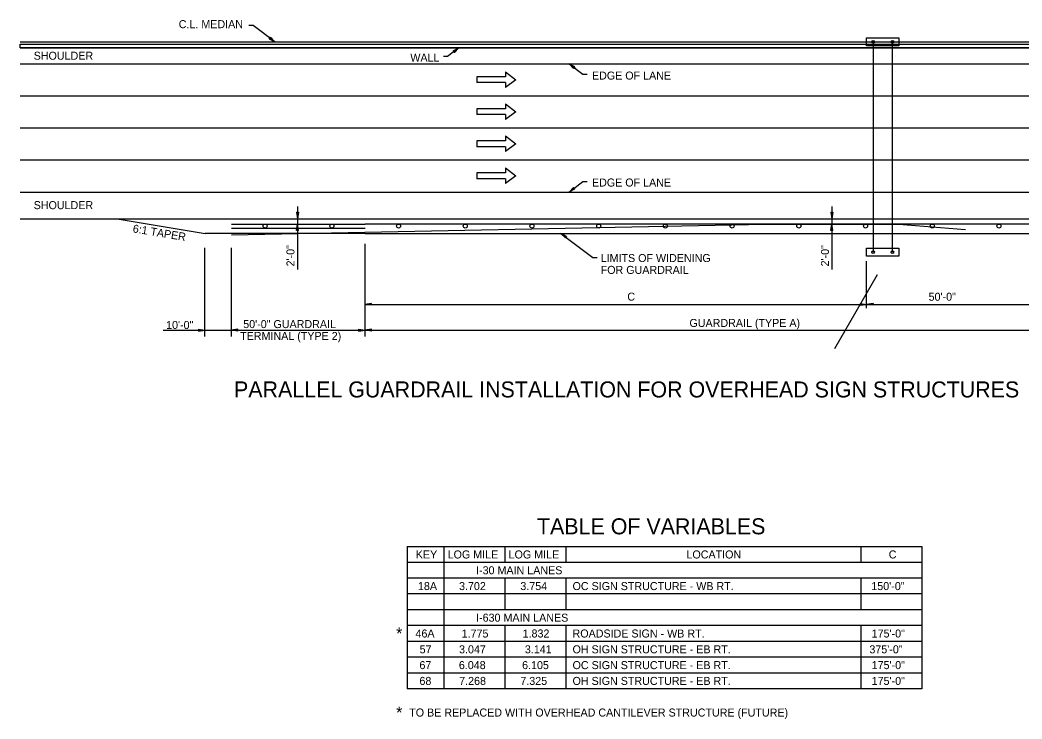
# Model space of a CAD drawing. Extents: x 1373853 to 1374003, y 380191 to 380927.
# Drawn here: x 1373877.3 to 1373952.4, y 380689.2 to 380741.6 of the extents above; entities that cross this region are included whole.
import ezdxf

# ---------------------------------------------------------------- set-up
doc = ezdxf.new("R2010")
doc.units = 0
for name, color, linetype in [('2', 7, 'Continuous'), ('44', 7, 'Continuous'), ('7', 7, 'Continuous'), ('8', 7, 'Continuous'), ('Default', 7, 'Continuous'), ('E_Existing ROW', 7, 'Continuous'), ('Plan Notes', 7, 'Continuous'), ('R_Draft', 7, 'Continuous'), ('R_Proposed Road', 7, 'Continuous'), ('R_SIGN_OH', 7, 'Continuous')]:
    doc.layers.add(name, color=color, linetype=linetype)

msp = doc.modelspace()

# ---------------------------------------------------------------- linework, layer by layer
at = {"layer": '2'}
for p, q in [((1373894.796, 380741.159), (1373894.477, 380741.159)), ((1373896.424, 380739.928), (1373894.796, 380741.159)), ((1373910.216, 380739.478), (1373909.369, 380738.838)), ((1373909.369, 380738.838), (1373909.05, 380738.838)), ((1373918.466, 380738.278), (1373919.498, 380737.498)), ((1373919.498, 380737.498), (1373919.818, 380737.498)), ((1373918.466, 380728.678), (1373919.498, 380729.459)), ((1373919.498, 380729.459), (1373919.818, 380729.459)), ((1373898.109, 380727.602), (1373898.109, 380722.881)), ((1373938.173, 380727.602), (1373938.173, 380722.881)), ((1373917.854, 380725.578), (1373920.253, 380723.765)), ((1373903.176, 380717.856), (1373903.176, 380724.807)), ((1373891.176, 380717.856), (1373891.176, 380724.492)), ((1373893.176, 380717.856), (1373893.176, 380724.492)), ((1373920.253, 380723.765), (1373920.572, 380723.765)), ((1373940.776, 380719.97), (1373940.776, 380723.499)), ((1373903.176, 380720.26), (1373967.577, 380720.26)), ((1373888.057, 380718.335), (1373962.85, 380718.335))]:
    msp.add_line(p, q, dxfattribs=at)
at = {"layer": '44'}
msp.add_line((1373877.32, 380726.678), (1373970.938, 380726.678), dxfattribs=at)
at = {"layer": '7'}
for p, q in [((1373895.997, 380740.16), (1373896.083, 380740.272)), ((1373895.997, 380740.16), (1373896.424, 380739.928)), ((1373896.003, 380740.167), (1373896.359, 380739.975)), ((1373896.012, 380740.177), (1373896.291, 380740.026)), ((1373896.019, 380740.187), (1373896.229, 380740.073)), ((1373896.028, 380740.197), (1373896.166, 380740.122)), ((1373896.032, 380740.21), (1373896.099, 380740.17)), ((1373896.048, 380740.225), (1373896.099, 380740.17)), ((1373896.054, 380740.235), (1373896.166, 380740.122)), ((1373896.061, 380740.242), (1373896.229, 380740.073)), ((1373896.065, 380740.252), (1373896.291, 380740.026)), ((1373896.074, 380740.265), (1373896.359, 380739.975)), ((1373896.083, 380740.272), (1373896.424, 380739.928)), ((1373909.789, 380739.247), (1373910.216, 380739.478)), ((1373909.789, 380739.247), (1373909.876, 380739.134)), ((1373909.795, 380739.239), (1373910.151, 380739.432)), ((1373909.804, 380739.229), (1373910.083, 380739.381)), ((1373909.811, 380739.219), (1373910.021, 380739.334)), ((1373909.82, 380739.209), (1373909.958, 380739.285)), ((1373909.824, 380739.197), (1373909.891, 380739.236)), ((1373909.84, 380739.182), (1373909.891, 380739.236)), ((1373909.847, 380739.172), (1373909.958, 380739.285)), ((1373909.853, 380739.164), (1373910.021, 380739.334)), ((1373909.858, 380739.154), (1373910.083, 380739.381)), ((1373909.866, 380739.142), (1373910.151, 380739.432)), ((1373909.876, 380739.134), (1373910.216, 380739.478)), ((1373918.893, 380738.047), (1373918.466, 380738.278)), ((1373918.806, 380737.934), (1373918.466, 380738.278)), ((1373918.886, 380738.039), (1373918.531, 380738.232)), ((1373918.815, 380737.942), (1373918.531, 380738.232)), ((1373918.824, 380737.954), (1373918.598, 380738.181)), ((1373918.877, 380738.029), (1373918.598, 380738.181)), ((1373918.871, 380738.019), (1373918.661, 380738.134)), ((1373918.828, 380737.964), (1373918.661, 380738.134)), ((1373918.835, 380737.972), (1373918.723, 380738.085)), ((1373918.862, 380738.009), (1373918.723, 380738.085)), ((1373918.842, 380737.982), (1373918.791, 380738.036)), ((1373918.858, 380737.997), (1373918.791, 380738.036)), ((1373918.893, 380738.047), (1373918.806, 380737.934)), ((1373918.806, 380729.022), (1373918.466, 380728.678)), ((1373918.893, 380728.91), (1373918.466, 380728.678)), ((1373918.815, 380729.015), (1373918.531, 380728.725)), ((1373918.886, 380728.917), (1373918.531, 380728.725)), ((1373918.824, 380729.002), (1373918.598, 380728.776)), ((1373918.877, 380728.927), (1373918.598, 380728.776)), ((1373918.828, 380728.992), (1373918.661, 380728.823)), ((1373918.871, 380728.937), (1373918.661, 380728.823)), ((1373918.835, 380728.985), (1373918.723, 380728.872)), ((1373918.862, 380728.947), (1373918.723, 380728.872)), ((1373918.842, 380728.975), (1373918.791, 380728.92)), ((1373918.858, 380728.96), (1373918.791, 380728.92)), ((1373918.893, 380728.91), (1373918.806, 380729.022)), ((1373898.035, 380727.158), (1373898.109, 380726.678)), ((1373898.035, 380727.158), (1373898.181, 380727.158)), ((1373898.05, 380727.158), (1373898.109, 380726.759)), ((1373898.062, 380727.158), (1373898.109, 380726.841)), ((1373898.074, 380727.158), (1373898.109, 380726.922)), ((1373898.086, 380727.158), (1373898.109, 380727.001)), ((1373898.097, 380727.158), (1373898.109, 380727.082)), ((1373898.181, 380727.158), (1373898.109, 380726.678)), ((1373898.131, 380727.158), (1373898.109, 380727.001)), ((1373898.155, 380727.158), (1373898.109, 380726.841)), ((1373898.169, 380727.158), (1373898.109, 380726.759)), ((1373898.145, 380727.158), (1373898.109, 380726.922)), ((1373898.119, 380727.158), (1373898.109, 380727.082)), ((1373938.099, 380727.158), (1373938.173, 380726.678)), ((1373938.099, 380727.158), (1373938.245, 380727.158)), ((1373938.114, 380727.158), (1373938.173, 380726.759)), ((1373938.126, 380727.158), (1373938.173, 380726.841)), ((1373938.138, 380727.158), (1373938.173, 380726.922)), ((1373938.15, 380727.158), (1373938.173, 380727.001)), ((1373938.161, 380727.158), (1373938.173, 380727.082)), ((1373938.245, 380727.158), (1373938.173, 380726.678)), ((1373938.195, 380727.158), (1373938.173, 380727.001)), ((1373938.219, 380727.158), (1373938.173, 380726.841)), ((1373938.233, 380727.158), (1373938.173, 380726.759)), ((1373938.209, 380727.158), (1373938.173, 380726.922)), ((1373938.183, 380727.158), (1373938.173, 380727.082)), ((1373898.038, 380725.798), (1373898.109, 380726.278)), ((1373898.181, 380725.798), (1373898.109, 380726.278)), ((1373938.102, 380725.798), (1373938.173, 380726.278)), ((1373938.245, 380725.798), (1373938.173, 380726.278)), ((1373898.181, 380725.798), (1373898.038, 380725.798)), ((1373898.05, 380725.798), (1373898.109, 380726.197)), ((1373898.062, 380725.798), (1373898.109, 380726.116)), ((1373898.074, 380725.798), (1373898.109, 380726.035)), ((1373898.086, 380725.798), (1373898.109, 380725.953)), ((1373898.097, 380725.798), (1373898.109, 380725.875)), ((1373898.169, 380725.798), (1373898.109, 380726.197)), ((1373898.157, 380725.798), (1373898.109, 380726.116)), ((1373898.145, 380725.798), (1373898.109, 380726.035)), ((1373898.133, 380725.798), (1373898.109, 380725.953)), ((1373898.121, 380725.798), (1373898.109, 380725.875)), ((1373918.281, 380725.347), (1373917.854, 380725.578)), ((1373918.194, 380725.234), (1373917.854, 380725.578)), ((1373918.274, 380725.339), (1373917.919, 380725.532)), ((1373918.203, 380725.242), (1373917.919, 380725.532)), ((1373938.245, 380725.798), (1373938.102, 380725.798)), ((1373938.114, 380725.798), (1373938.173, 380726.197)), ((1373938.126, 380725.798), (1373938.173, 380726.116)), ((1373938.138, 380725.798), (1373938.173, 380726.035)), ((1373938.15, 380725.798), (1373938.173, 380725.953)), ((1373938.161, 380725.798), (1373938.173, 380725.875)), ((1373938.233, 380725.798), (1373938.173, 380726.197)), ((1373938.221, 380725.798), (1373938.173, 380726.116)), ((1373938.209, 380725.798), (1373938.173, 380726.035)), ((1373938.197, 380725.798), (1373938.173, 380725.953)), ((1373938.185, 380725.798), (1373938.173, 380725.875)), ((1373918.212, 380725.254), (1373917.986, 380725.481)), ((1373918.265, 380725.329), (1373917.986, 380725.481)), ((1373918.259, 380725.319), (1373918.049, 380725.434)), ((1373918.216, 380725.264), (1373918.049, 380725.434)), ((1373918.223, 380725.272), (1373918.111, 380725.385)), ((1373918.25, 380725.309), (1373918.111, 380725.385)), ((1373918.23, 380725.282), (1373918.179, 380725.336)), ((1373918.246, 380725.297), (1373918.179, 380725.336)), ((1373918.281, 380725.347), (1373918.194, 380725.234)), ((1373903.653, 380720.331), (1373903.176, 380720.26)), ((1373903.653, 380720.188), (1373903.176, 380720.26)), ((1373903.653, 380720.319), (1373903.254, 380720.26)), ((1373903.653, 380720.2), (1373903.254, 380720.26)), ((1373903.653, 380720.307), (1373903.338, 380720.26)), ((1373903.653, 380720.212), (1373903.338, 380720.26)), ((1373903.653, 380720.295), (1373903.419, 380720.26)), ((1373903.653, 380720.224), (1373903.419, 380720.26)), ((1373903.653, 380720.283), (1373903.498, 380720.26)), ((1373903.653, 380720.236), (1373903.498, 380720.26)), ((1373903.653, 380720.269), (1373903.579, 380720.26)), ((1373903.653, 380720.248), (1373903.579, 380720.26)), ((1373903.653, 380720.188), (1373903.653, 380720.331)), ((1373940.296, 380720.334), (1373940.776, 380720.26)), ((1373940.296, 380720.334), (1373940.296, 380720.188)), ((1373940.296, 380720.319), (1373940.694, 380720.26)), ((1373940.296, 380720.307), (1373940.613, 380720.26)), ((1373940.296, 380720.295), (1373940.532, 380720.26)), ((1373940.296, 380720.283), (1373940.453, 380720.26)), ((1373940.296, 380720.272), (1373940.372, 380720.26)), ((1373940.296, 380720.188), (1373940.776, 380720.26)), ((1373940.296, 380720.238), (1373940.453, 380720.26)), ((1373940.296, 380720.214), (1373940.613, 380720.26)), ((1373940.296, 380720.2), (1373940.694, 380720.26)), ((1373940.296, 380720.224), (1373940.532, 380720.26)), ((1373940.296, 380720.25), (1373940.372, 380720.26)), ((1373941.256, 380720.334), (1373940.776, 380720.26)), ((1373941.256, 380720.188), (1373940.776, 380720.26)), ((1373941.256, 380720.319), (1373940.857, 380720.26)), ((1373941.256, 380720.2), (1373940.857, 380720.26)), ((1373941.256, 380720.307), (1373940.938, 380720.26)), ((1373941.256, 380720.214), (1373940.938, 380720.26)), ((1373941.256, 380720.295), (1373941.019, 380720.26)), ((1373941.256, 380720.224), (1373941.019, 380720.26)), ((1373941.256, 380720.283), (1373941.098, 380720.26)), ((1373941.256, 380720.238), (1373941.098, 380720.26)), ((1373941.256, 380720.272), (1373941.179, 380720.26)), ((1373941.256, 380720.25), (1373941.179, 380720.26)), ((1373941.256, 380720.334), (1373941.256, 380720.188)), ((1373890.696, 380718.407), (1373891.176, 380718.335)), ((1373890.696, 380718.407), (1373890.696, 380718.263)), ((1373890.696, 380718.395), (1373891.094, 380718.335)), ((1373890.696, 380718.383), (1373891.011, 380718.335)), ((1373890.696, 380718.371), (1373890.932, 380718.335)), ((1373890.696, 380718.359), (1373890.853, 380718.335)), ((1373890.696, 380718.347), (1373890.772, 380718.335)), ((1373890.696, 380718.263), (1373891.176, 380718.335)), ((1373890.696, 380718.311), (1373890.853, 380718.335)), ((1373890.696, 380718.287), (1373891.011, 380718.335)), ((1373890.696, 380718.275), (1373891.094, 380718.335)), ((1373890.696, 380718.299), (1373890.932, 380718.335)), ((1373890.696, 380718.323), (1373890.772, 380718.335)), ((1373893.653, 380718.407), (1373893.176, 380718.335)), ((1373893.653, 380718.263), (1373893.176, 380718.335)), ((1373893.653, 380718.395), (1373893.254, 380718.335)), ((1373893.653, 380718.275), (1373893.254, 380718.335)), ((1373893.653, 380718.383), (1373893.338, 380718.335)), ((1373893.653, 380718.287), (1373893.338, 380718.335)), ((1373893.653, 380718.371), (1373893.419, 380718.335)), ((1373893.653, 380718.299), (1373893.419, 380718.335)), ((1373893.653, 380718.359), (1373893.498, 380718.335)), ((1373893.653, 380718.311), (1373893.498, 380718.335)), ((1373893.653, 380718.345), (1373893.579, 380718.335)), ((1373893.653, 380718.323), (1373893.579, 380718.335)), ((1373893.653, 380718.263), (1373893.653, 380718.407)), ((1373902.696, 380718.407), (1373903.176, 380718.335)), ((1373902.696, 380718.407), (1373902.696, 380718.263)), ((1373902.696, 380718.395), (1373903.094, 380718.335)), ((1373902.696, 380718.383), (1373903.011, 380718.335)), ((1373902.696, 380718.371), (1373902.932, 380718.335)), ((1373902.696, 380718.359), (1373902.853, 380718.335)), ((1373902.696, 380718.347), (1373902.772, 380718.335)), ((1373902.696, 380718.263), (1373903.176, 380718.335)), ((1373902.696, 380718.311), (1373902.853, 380718.335)), ((1373902.696, 380718.287), (1373903.011, 380718.335)), ((1373902.696, 380718.275), (1373903.094, 380718.335)), ((1373902.696, 380718.299), (1373902.932, 380718.335)), ((1373902.696, 380718.323), (1373902.772, 380718.335)), ((1373903.653, 380718.407), (1373903.176, 380718.335)), ((1373903.653, 380718.263), (1373903.176, 380718.335)), ((1373903.653, 380718.395), (1373903.254, 380718.335)), ((1373903.653, 380718.275), (1373903.254, 380718.335)), ((1373903.653, 380718.383), (1373903.338, 380718.335)), ((1373903.653, 380718.287), (1373903.338, 380718.335)), ((1373903.653, 380718.371), (1373903.419, 380718.335)), ((1373903.653, 380718.299), (1373903.419, 380718.335)), ((1373903.653, 380718.359), (1373903.498, 380718.335)), ((1373903.653, 380718.311), (1373903.498, 380718.335)), ((1373903.653, 380718.345), (1373903.579, 380718.335)), ((1373903.653, 380718.323), (1373903.579, 380718.335)), ((1373903.653, 380718.263), (1373903.653, 380718.407))]:
    msp.add_line(p, q, dxfattribs=at)
at = {"layer": 'Default'}
for p, q in [((1373913.712, 380737.683), (1373913.712, 380737.316)), ((1373913.712, 380737.683), (1373914.475, 380737.096)), ((1373913.712, 380737.316), (1373911.551, 380737.316)), ((1373911.551, 380737.316), (1373911.551, 380736.875)), ((1373913.712, 380736.875), (1373911.551, 380736.875)), ((1373914.475, 380737.096), (1373913.712, 380736.508)), ((1373913.712, 380736.875), (1373913.712, 380736.508)), ((1373913.712, 380735.283), (1373913.712, 380734.916)), ((1373913.712, 380735.283), (1373914.475, 380734.696)), ((1373913.712, 380734.916), (1373911.551, 380734.916)), ((1373911.551, 380734.916), (1373911.551, 380734.475)), ((1373914.475, 380734.696), (1373913.712, 380734.108)), ((1373913.712, 380734.475), (1373911.551, 380734.475)), ((1373913.712, 380734.475), (1373913.712, 380734.108)), ((1373913.712, 380732.516), (1373911.551, 380732.516)), ((1373911.551, 380732.516), (1373911.551, 380732.075)), ((1373913.712, 380732.883), (1373913.712, 380732.516)), ((1373913.712, 380732.883), (1373914.475, 380732.296)), ((1373914.475, 380732.296), (1373913.712, 380731.708)), ((1373913.712, 380732.075), (1373911.551, 380732.075)), ((1373913.712, 380732.075), (1373913.712, 380731.708)), ((1373913.712, 380730.116), (1373911.551, 380730.116)), ((1373911.551, 380730.116), (1373911.551, 380729.675)), ((1373913.712, 380730.483), (1373913.712, 380730.116)), ((1373913.712, 380730.483), (1373914.475, 380729.896)), ((1373913.712, 380729.675), (1373911.551, 380729.675)), ((1373914.475, 380729.896), (1373913.712, 380729.308)), ((1373913.712, 380729.675), (1373913.712, 380729.308))]:
    msp.add_line(p, q, dxfattribs=at)
at = {"layer": 'E_Existing ROW'}
msp.add_lwpolyline([(1373938.379, 380716.957), (1373941.576, 380722.493)], dxfattribs=at)
msp.add_lwpolyline([(1373938.379, 380716.957), (1373941.576, 380722.493)], dxfattribs=at)
at = {"layer": 'Plan Notes'}
for p, q in [((1373906.332, 380702.112), (1373944.903, 380702.112)), ((1373906.332, 380702.112), (1373906.332, 380691.451)), ((1373909.089, 380702.112), (1373909.089, 380691.451)), ((1373913.658, 380702.112), (1373913.658, 380700.928)), ((1373918.228, 380702.112), (1373918.228, 380700.928)), ((1373940.333, 380702.112), (1373940.333, 380700.928)), ((1373944.903, 380702.112), (1373944.903, 380691.451)), ((1373913.658, 380699.743), (1373913.658, 380697.374)), ((1373918.228, 380699.743), (1373918.228, 380697.374)), ((1373940.333, 380699.743), (1373940.333, 380697.374)), ((1373913.658, 380696.19), (1373913.658, 380691.451)), ((1373918.228, 380696.19), (1373918.228, 380691.451)), ((1373940.333, 380696.19), (1373940.333, 380691.451))]:
    msp.add_line(p, q, dxfattribs=at)
for points in [[(1373944.903, 380700.928), (1373906.332, 380700.928)], [(1373944.903, 380699.743), (1373906.332, 380699.743)], [(1373944.903, 380698.559), (1373906.332, 380698.559)], [(1373944.903, 380697.374), (1373906.332, 380697.374)], [(1373944.903, 380696.19), (1373906.332, 380696.19)], [(1373944.903, 380695.005), (1373906.332, 380695.005)], [(1373944.903, 380693.82), (1373906.332, 380693.82)], [(1373944.903, 380692.636), (1373906.332, 380692.636)], [(1373944.903, 380691.451), (1373906.332, 380691.451)]]:
    msp.add_lwpolyline(points, dxfattribs=at)
at = {"layer": 'R_Draft'}
msp.add_lwpolyline([(1373877.32, 380739.748), (1373970.938, 380739.748), (1373970.938, 380739.478), (1373877.32, 380739.478)], close=True, dxfattribs=at)
at = {"layer": 'R_Proposed Road'}
for p, q in [((1373877.32, 380739.928), (1373970.938, 380739.928)), ((1373877.32, 380739.748), (1373970.938, 380739.748)), ((1373877.32, 380739.478), (1373970.938, 380739.478)), ((1373877.32, 380738.278), (1373970.938, 380738.278)), ((1373877.32, 380735.878), (1373970.938, 380735.878)), ((1373877.32, 380733.478), (1373970.938, 380733.478)), ((1373877.32, 380731.078), (1373970.938, 380731.078)), ((1373877.32, 380728.678), (1373970.938, 380728.678)), ((1373884.594, 380726.676), (1373891.194, 380725.576)), ((1373893.174, 380726.276), (1373903.176, 380726.278)), ((1373893.176, 380725.478), (1373933.176, 380726.278)), ((1373933.176, 380726.278), (1373943.176, 380726.278)), ((1373943.176, 380726.278), (1373948.176, 380725.878)), ((1373903.196, 380725.578), (1373891.194, 380725.576)), ((1373893.174, 380725.979), (1373903.176, 380725.981))]:
    msp.add_line(p, q, dxfattribs=at)
for points in [[(1373905.692, 380726.278), (1373903.176, 380726.278)], [(1373908.192, 380726.278), (1373905.692, 380726.278)], [(1373910.692, 380726.278), (1373908.192, 380726.278)], [(1373915.692, 380726.278), (1373910.692, 380726.278)], [(1373918.192, 380726.278), (1373915.692, 380726.278)], [(1373920.692, 380726.278), (1373918.192, 380726.278)], [(1373925.692, 380726.278), (1373920.692, 380726.278)], [(1373928.192, 380726.278), (1373925.692, 380726.278)], [(1373930.692, 380726.278), (1373928.192, 380726.278)], [(1373933.176, 380726.278), (1373930.692, 380726.278)], [(1373935.692, 380726.278), (1373933.176, 380726.278)], [(1373938.192, 380726.278), (1373935.692, 380726.278)], [(1373940.692, 380726.278), (1373938.192, 380726.278)], [(1373958.176, 380725.878), (1373953.176, 380726.278), (1373940.692, 380726.278)], [(1373903.196, 380725.578), (1373933.183, 380725.578)], [(1373933.183, 380725.578), (1373960.176, 380725.578)]]:
    msp.add_lwpolyline(points, dxfattribs=at)
for centre in [(1373895.692, 380726.129), (1373900.692, 380726.129), (1373905.692, 380726.129), (1373910.692, 380726.129), (1373915.692, 380726.129), (1373920.692, 380726.129), (1373925.692, 380726.129), (1373930.692, 380726.129), (1373935.692, 380726.129), (1373940.692, 380726.129), (1373945.692, 380726.129), (1373950.692, 380726.129)]:
    msp.add_circle(centre, 0.15, dxfattribs=at)
at = {"layer": 'R_SIGN_OH'}
for p, q in [((1373940.776, 380740.228), (1373943.176, 380740.228)), ((1373940.776, 380739.628), (1373940.776, 380740.228)), ((1373941.251, 380739.928), (1373941.251, 380735.878)), ((1373942.701, 380735.878), (1373942.701, 380739.928)), ((1373943.176, 380740.228), (1373943.176, 380739.628)), ((1373943.176, 380739.628), (1373940.776, 380739.628)), ((1373941.251, 380735.878), (1373941.251, 380724.178)), ((1373942.701, 380724.178), (1373942.701, 380735.878)), ((1373940.776, 380724.478), (1373943.176, 380724.478)), ((1373940.776, 380723.878), (1373940.776, 380724.478)), ((1373943.176, 380724.478), (1373943.176, 380723.878)), ((1373943.176, 380723.878), (1373940.776, 380723.878))]:
    msp.add_line(p, q, dxfattribs=at)
for centre in [(1373941.251, 380739.928), (1373942.701, 380739.928), (1373941.251, 380724.178), (1373942.701, 380724.178)]:
    msp.add_circle(centre, 0.1, dxfattribs=at)

# ---------------------------------------------------------------- texts
at = {"layer": '2'}
for s, height, rotation, p in [('C.L. MEDIAN', 0.6, 0.00003, (1373889.217, 380740.955)), ('SHOULDER', 0.6, 0.00003, (1373878.343, 380738.591)), ('WALL', 0.6, 359.99997, (1373906.573, 380738.442)), ('EDGE OF LANE', 0.6, 0.00003, (1373920.187, 380737.102)), ('EDGE OF LANE', 0.6, 0.00003, (1373920.187, 380729.088)), ('SHOULDER', 0.6, 0.00003, (1373878.343, 380727.394)), ('6:1 TAPER', 0.6, 350.53773, (1373885.738, 380725.663)), ('2\'-0"', 0.6, 89.99997, (1373897.888, 380723.102)), ('LIMITS OF WIDENING', 0.6, 0.00003, (1373920.84, 380723.431)), ('2\'-0"', 0.6, 89.99997, (1373937.952, 380723.102)), ('FOR GUARDRAIL', 0.6, 0.00003, (1373920.84, 380722.542)), ('C', 0.6, 0.00003, (1373922.836, 380720.538)), ('50\'-0"', 0.6, 0.00003, (1373945.419, 380720.532)), ('10\'-0"', 0.6, 0.00003, (1373888.268, 380718.415)), ('50\'-0" GUARDRAIL', 0.6, 0.00003, (1373894.049, 380718.482)), ('GUARDRAIL (TYPE A)', 0.6, 0.00003, (1373927.494, 380718.566)), ('TERMINAL (TYPE 2)', 0.6, 0.00003, (1373893.817, 380717.592)), ('KEY', 0.6, 0.00003, (1373906.983, 380701.22)), ('LOG MILE', 0.6, 0.00003, (1373909.37, 380701.22)), ('LOG MILE', 0.6, 0.00003, (1373913.94, 380701.22)), ('LOCATION', 0.6, 0.00003, (1373927.27, 380701.22)), ('C', 0.6, 0.00003, (1373942.431, 380701.22)), ('I-30 MAIN LANES', 0.6, 0.00003, (1373911.502, 380700.035)), ('18A', 0.6, 0.00003, (1373907.146, 380698.851)), ('3.702', 0.6, 0.00003, (1373910.225, 380698.851)), ('3.754', 0.6, 0.00003, (1373914.819, 380698.851)), ('OC SIGN STRUCTURE - WB RT.', 0.6, 0.00003, (1373918.732, 380698.851)), ('150\'-0"', 0.6, 0.00003, (1373941.127, 380698.851)), ('I-630 MAIN LANES', 0.6, 0.00003, (1373911.502, 380696.482)), ('*', 0.9, 0.00003, (1373905.51, 380695.147)), ('46A', 0.6, 0.00003, (1373906.961, 380695.297)), ('1.775', 0.6, 0.00003, (1373910.419, 380695.297)), ('1.832', 0.6, 0.00003, (1373914.989, 380695.297)), ('ROADSIDE SIGN - WB RT.', 0.6, 0.00003, (1373918.732, 380695.297)), ('175\'-0"', 0.6, 0.00003, (1373941.151, 380695.297)), ('57', 0.6, 0.00003, (1373907.271, 380694.113)), ('3.047', 0.6, 0.00003, (1373910.225, 380694.113)), ('3.141', 0.6, 0.00003, (1373915.159, 380694.113)), ('OH SIGN STRUCTURE - EB RT.', 0.6, 0.00003, (1373918.732, 380694.113)), ('375\'-0"', 0.6, 0.00003, (1373940.981, 380694.113)), ('67', 0.6, 0.00003, (1373907.257, 380692.928)), ('6.048', 0.6, 0.00003, (1373910.211, 380692.928)), ('6.105', 0.6, 0.00003, (1373914.951, 380692.928)), ('OC SIGN STRUCTURE - EB RT.', 0.6, 0.00003, (1373918.732, 380692.928)), ('175\'-0"', 0.6, 0.00003, (1373941.151, 380692.928)), ('68', 0.6, 0.00003, (1373907.257, 380691.744)), ('7.268', 0.6, 0.00003, (1373910.235, 380691.744)), ('7.325', 0.6, 0.00003, (1373914.819, 380691.744)), ('OH SIGN STRUCTURE - EB RT.', 0.6, 0.00003, (1373918.732, 380691.744)), ('175\'-0"', 0.6, 0.00003, (1373941.151, 380691.744)), ('*', 0.9, 0.00003, (1373905.51, 380689.225)), ('TO BE REPLACED WITH OVERHEAD CANTILEVER STRUCTURE (FUTURE)', 0.6, 0.00003, (1373906.491, 380689.375))]:
    msp.add_text(s, height=height, rotation=rotation, dxfattribs=at).set_placement(p)
at = {"layer": '8'}
for s, p in [('PARALLEL GUARDRAIL INSTALLATION FOR OVERHEAD SIGN STRUCTURES', (1373893.359, 380713.285)), ('TABLE OF VARIABLES', (1373916.065, 380703.029))]:
    msp.add_text(s, height=1.2, rotation=0.00003, dxfattribs=at).set_placement(p)

doc.saveas('drawing.dxf')
